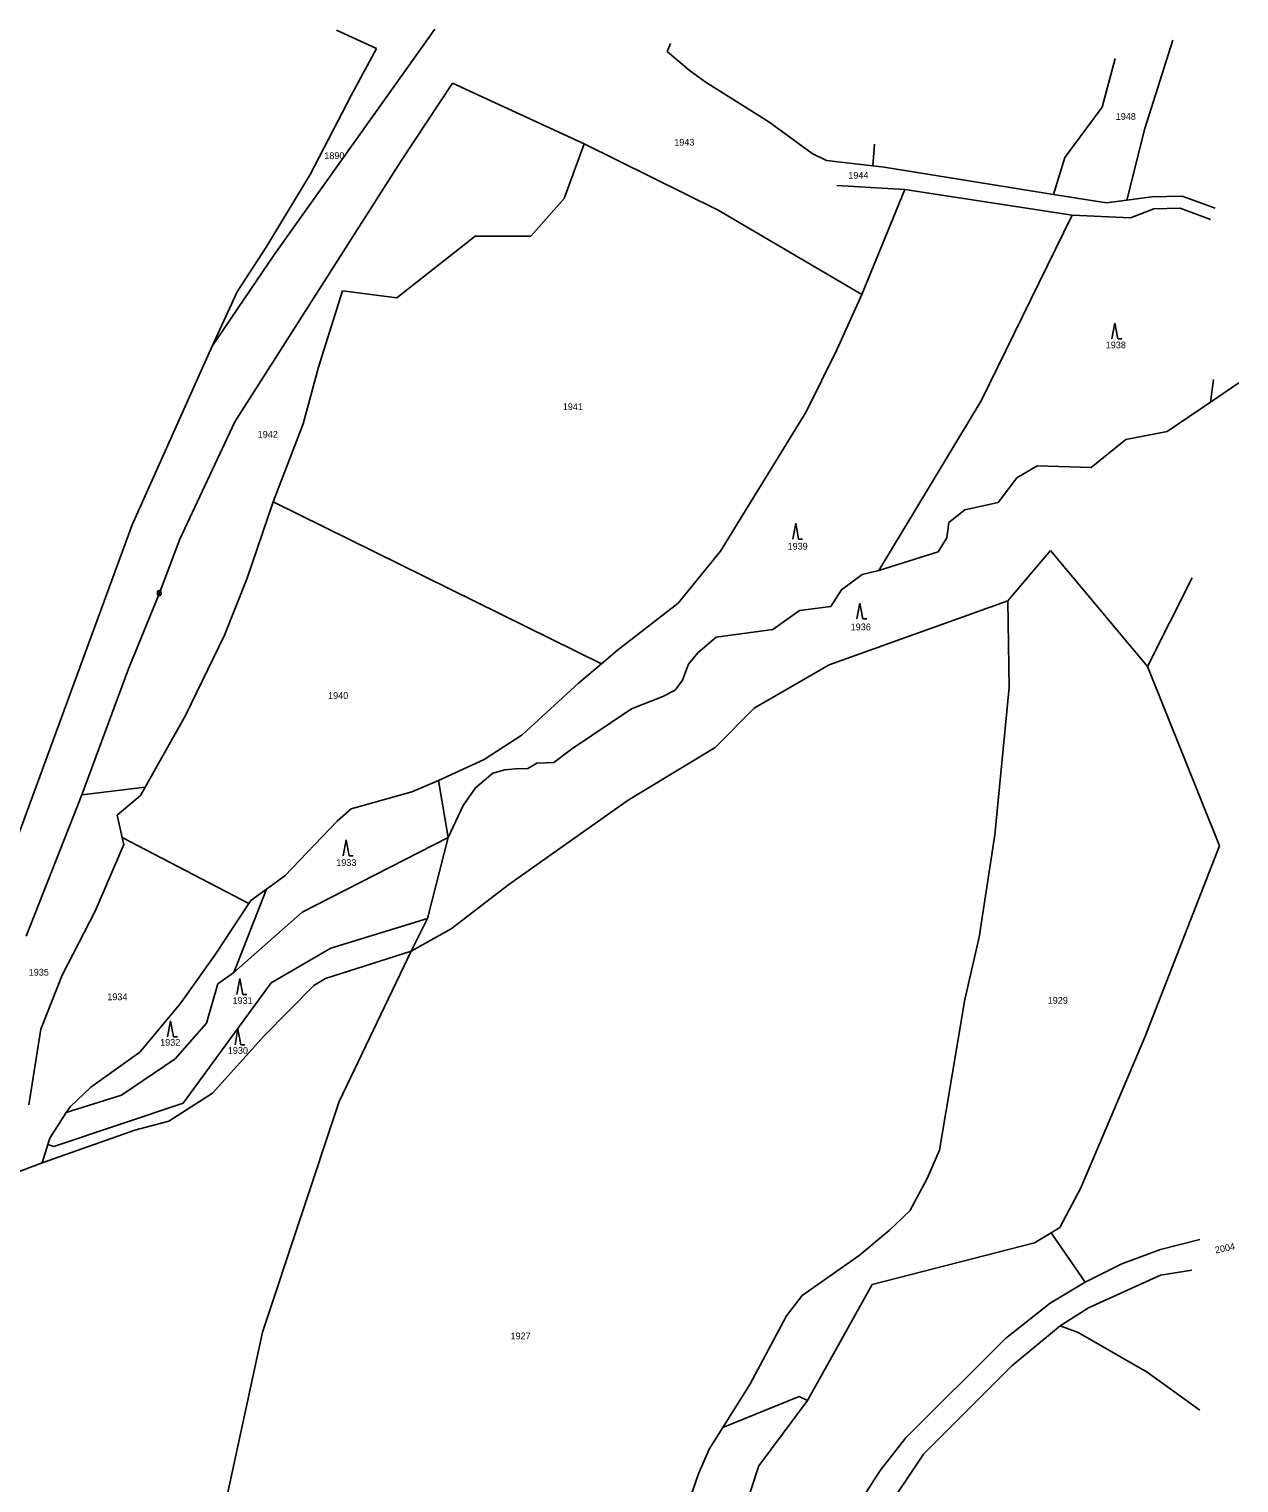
# Model space of a CAD drawing. Extents: x -801826 to -800592, y -1032871 to -1031813.
# Drawn here: x -800896.7 to -800592.7, y -1032178.1 to -1031812.7 of the extents above; entities that cross this region are included whole.
import ezdxf

# ---------------------------------------------------------------- set-up
doc = ezdxf.new("R2010")
doc.units = 0
for name, color, linetype in [('Vrstva 1', 7, 'Continuous'), ('Vrstva 18', 7, 'Continuous'), ('Vrstva 24', 7, 'Continuous'), ('Vrstva 25', 7, 'Continuous')]:
    doc.layers.add(name, color=color, linetype=linetype)

msp = doc.modelspace()

# ---------------------------------------------------------------- linework, layer by layer
at = {"layer": 'Vrstva 1'}
for p, q in [((-800794.72, -1031812.74), (-800834.92, -1031869.25)), ((-800819.49, -1031813), (-800809.4, -1031817.63)), ((-800735.53, -1031816.37), (-800736.38, -1031818.41)), ((-800616.36, -1031837.7), (-800609.3, -1031815.54)), ((-800815.75, -1031829.46), (-800809.4, -1031817.63)), ((-800730.87, -1031823.09), (-800736.38, -1031818.41)), ((-800623.79, -1031820.13), (-800627.09, -1031832.37)), ((-800726.8, -1031825.99), (-800730.87, -1031823.09)), ((-800803.37, -1031846.11), (-800790.33, -1031826.37)), ((-800757.2, -1031841.57), (-800790.33, -1031826.37)), ((-800710.79, -1031836.04), (-800726.8, -1031825.99)), ((-800826.05, -1031849.33), (-800815.75, -1031829.46)), ((-800627.09, -1031832.37), (-800636.49, -1031845.01)), ((-800699.93, -1031844), (-800710.79, -1031836.04)), ((-800620.85, -1031855.72), (-800616.36, -1031837.7)), ((-800762.25, -1031855.35), (-800757.2, -1031841.57)), ((-800757.2, -1031841.57), (-800723.58, -1031858.23)), ((-800684.7, -1031847.13), (-800684.25, -1031841.7)), ((-800696.34, -1031845.76), (-800699.93, -1031844)), ((-800684.7, -1031847.13), (-800696.34, -1031845.76)), ((-800636.49, -1031845.01), (-800639.27, -1031854.29)), ((-800845, -1031911.47), (-800803.37, -1031846.11)), ((-800837.11, -1031867.58), (-800826.05, -1031849.33)), ((-800681.88, -1031847.46), (-800684.7, -1031847.13)), ((-800639.27, -1031854.29), (-800681.88, -1031847.46)), ((-800693.74, -1031852.05), (-800676.64, -1031853.05)), ((-800676.64, -1031853.05), (-800687.5, -1031879.48)), ((-800676.64, -1031853.05), (-800634.57, -1031859.51)), ((-800770.59, -1031864.81), (-800762.25, -1031855.35)), ((-800626, -1031856.42), (-800639.27, -1031854.29)), ((-800620.85, -1031855.72), (-800626, -1031856.42)), ((-800614.71, -1031854.89), (-800620.85, -1031855.72)), ((-800607, -1031854.74), (-800614.71, -1031854.89)), ((-800598.7, -1031857.79), (-800607, -1031854.74)), ((-800723.58, -1031858.23), (-800687.5, -1031879.48)), ((-800657.45, -1031906.19), (-800634.57, -1031859.51)), ((-800634.57, -1031859.51), (-800619.94, -1031860.2)), ((-800619.94, -1031860.2), (-800614.11, -1031857.88)), ((-800614.11, -1031857.88), (-800607.51, -1031857.75)), ((-800607.51, -1031857.75), (-800599.87, -1031860.56)), ((-800844.38, -1031878.74), (-800837.11, -1031867.58)), ((-800804.3, -1031880.28), (-800784.63, -1031864.8)), ((-800784.63, -1031864.8), (-800770.59, -1031864.81)), ((-800834.92, -1031869.25), (-800850.7, -1031892.46)), ((-800823.97, -1031897.68), (-800817.92, -1031878.55)), ((-800817.92, -1031878.55), (-800804.3, -1031880.28)), ((-800850.7, -1031892.46), (-800844.38, -1031878.74)), ((-800687.5, -1031879.48), (-800693.77, -1031893.38)), ((-800850.7, -1031892.46), (-800870.77, -1031937.34)), ((-800693.77, -1031893.38), (-800701.44, -1031908.93)), ((-800827.84, -1031911.94), (-800823.97, -1031897.68)), ((-800599.88, -1031906.49), (-800599.09, -1031900.8)), ((-800592.71, -1031901.64), (-800599.88, -1031906.49)), ((-800683.21, -1031948.84), (-800657.45, -1031906.19)), ((-800599.88, -1031906.49), (-800610.76, -1031913.85)), ((-800858.84, -1031940.91), (-800845, -1031911.47)), ((-800701.44, -1031908.93), (-800722.96, -1031943.96)), ((-800835.33, -1031931.59), (-800827.84, -1031911.94)), ((-800610.76, -1031913.85), (-800621.1, -1031915.87)), ((-800621.1, -1031915.87), (-800629.85, -1031922.9)), ((-800648.49, -1031925.5), (-800653.17, -1031931.76)), ((-800643.39, -1031922.52), (-800648.49, -1031925.5)), ((-800629.85, -1031922.9), (-800643.39, -1031922.52)), ((-800841.93, -1031950.76), (-800835.33, -1031931.59)), ((-800752.91, -1031972.24), (-800835.33, -1031931.59)), ((-800653.17, -1031931.76), (-800661.55, -1031933.54)), ((-800665.57, -1031936.73), (-800666.12, -1031940.64)), ((-800661.55, -1031933.54), (-800665.57, -1031936.73)), ((-800870.77, -1031937.34), (-800899.17, -1032014.78)), ((-800666.12, -1031940.64), (-800668.31, -1031944.1)), ((-800864.01, -1031954.66), (-800858.84, -1031940.91)), ((-800722.96, -1031943.96), (-800733.57, -1031957.01)), ((-800668.31, -1031944.1), (-800683.21, -1031948.84)), ((-800650.8, -1031956.43), (-800640.07, -1031943.81)), ((-800640.07, -1031943.81), (-800615.65, -1031972.93)), ((-800847.59, -1031965.06), (-800841.93, -1031950.76)), ((-800692.56, -1031953.64), (-800687.41, -1031949.82)), ((-800687.41, -1031949.82), (-800683.21, -1031948.84)), ((-800604.42, -1031950.62), (-800615.65, -1031972.93)), ((-800871.72, -1031973.5), (-800864.01, -1031954.66)), ((-800695.28, -1031957.86), (-800692.56, -1031953.64)), ((-800733.57, -1031957.01), (-800748.84, -1031968.8)), ((-800709.84, -1031963.61), (-800703.11, -1031958.86)), ((-800703.11, -1031958.86), (-800695.28, -1031957.86)), ((-800695.63, -1031972.54), (-800650.8, -1031956.43)), ((-800650.8, -1031956.43), (-800650.43, -1031978.22)), ((-800857.42, -1031985.29), (-800847.59, -1031965.06)), ((-800728.67, -1031969.54), (-800724.04, -1031965.6)), ((-800724.04, -1031965.6), (-800709.84, -1031963.61)), ((-800748.84, -1031968.8), (-800752.91, -1031972.24)), ((-800731.01, -1031972.32), (-800728.67, -1031969.54)), ((-800883.47, -1032005.21), (-800871.72, -1031973.5)), ((-800752.91, -1031972.24), (-800758.68, -1031977.12)), ((-800732.56, -1031976.42), (-800731.01, -1031972.32)), ((-800714.48, -1031983.45), (-800695.63, -1031972.54)), ((-800615.65, -1031972.93), (-800597.63, -1032018.04)), ((-800758.68, -1031977.12), (-800772.81, -1031990.11)), ((-800734.36, -1031978.93), (-800732.56, -1031976.42)), ((-800745.32, -1031983.56), (-800737.45, -1031980.52)), ((-800737.45, -1031980.52), (-800734.36, -1031978.93)), ((-800650.43, -1031978.22), (-800654.02, -1032015.22)), ((-800760.39, -1031993.73), (-800745.32, -1031983.56)), ((-800724.34, -1031993.26), (-800714.48, -1031983.45)), ((-800857.42, -1031985.29), (-800867.57, -1032003.29)), ((-800772.81, -1031990.11), (-800782.38, -1031996.28)), ((-800764.86, -1031997.1), (-800760.39, -1031993.73)), ((-800746.18, -1032006.53), (-800724.34, -1031993.26)), ((-800782.38, -1031996.28), (-800793.84, -1032001.63)), ((-800780.16, -1031999.77), (-800777.18, -1031998.88)), ((-800777.18, -1031998.88), (-800774.44, -1031998.66)), ((-800774.44, -1031998.66), (-800771.4, -1031998.6)), ((-800771.4, -1031998.6), (-800769.08, -1031997.24)), ((-800769.08, -1031997.24), (-800764.86, -1031997.1)), ((-800793.84, -1032001.63), (-800800.56, -1032004.44)), ((-800793.84, -1032001.63), (-800791.36, -1032015.91)), ((-800784.57, -1032003.43), (-800780.16, -1031999.77)), ((-800897.43, -1032040.71), (-800883.47, -1032005.21)), ((-800883.47, -1032005.21), (-800867.57, -1032003.29)), ((-800874.53, -1032010.29), (-800868.73, -1032005.34)), ((-800867.57, -1032003.29), (-800868.73, -1032005.34)), ((-800800.56, -1032004.44), (-800815.76, -1032008.75)), ((-800787.61, -1032007.9), (-800784.57, -1032003.43)), ((-800776.15, -1032027.74), (-800746.18, -1032006.53)), ((-800815.76, -1032008.75), (-800819.31, -1032011.8)), ((-800791.36, -1032015.91), (-800787.61, -1032007.9)), ((-800873.28, -1032015.9), (-800874.53, -1032010.29)), ((-800819.31, -1032011.8), (-800832.46, -1032025.57)), ((-800872.89, -1032017.68), (-800873.28, -1032015.9)), ((-800841.45, -1032032.47), (-800873.28, -1032015.9)), ((-800828.11, -1032034.72), (-800791.36, -1032015.91)), ((-800796.62, -1032036.3), (-800791.36, -1032015.91)), ((-800654.02, -1032015.22), (-800657.95, -1032040.96)), ((-800880.13, -1032034.43), (-800872.89, -1032017.68)), ((-800597.63, -1032018.04), (-800616.35, -1032066.13)), ((-800832.46, -1032025.57), (-800837.08, -1032028.93)), ((-800790.61, -1032038.89), (-800776.15, -1032027.74)), ((-800845.22, -1032049.84), (-800837.08, -1032028.93)), ((-800840.99, -1032031.77), (-800841.45, -1032032.47)), ((-800837.08, -1032028.93), (-800840.99, -1032031.77)), ((-800888.39, -1032050.53), (-800880.13, -1032034.43)), ((-800841.45, -1032032.47), (-800850.03, -1032045.49)), ((-800845.22, -1032049.84), (-800828.11, -1032034.72)), ((-800820.9, -1032043.71), (-800796.62, -1032036.3)), ((-800800.72, -1032044.51), (-800796.62, -1032036.3)), ((-800800.72, -1032044.51), (-800790.61, -1032038.89)), ((-800657.95, -1032040.96), (-800661.54, -1032056.66)), ((-800850.03, -1032045.49), (-800858.78, -1032057.73)), ((-800835.89, -1032052.43), (-800820.9, -1032043.71)), ((-800822.24, -1032051.34), (-800800.72, -1032044.51)), ((-800800.72, -1032044.51), (-800818.82, -1032082.28)), ((-800849.24, -1032052.66), (-800845.22, -1032049.84)), ((-800893.77, -1032064.12), (-800888.39, -1032050.53)), ((-800858, -1032082.67), (-800835.89, -1032052.43)), ((-800852.15, -1032062.62), (-800849.24, -1032052.66)), ((-800837.6, -1032065.74), (-800825.18, -1032053.11)), ((-800825.18, -1032053.11), (-800822.24, -1032051.34)), ((-800661.54, -1032056.66), (-800667.98, -1032094.53)), ((-800858.78, -1032057.73), (-800868.91, -1032069.9)), ((-800896.78, -1032083.1), (-800893.77, -1032064.12)), ((-800860.01, -1032071.52), (-800852.15, -1032062.62)), ((-800850.6, -1032080.16), (-800837.6, -1032065.74)), ((-800616.35, -1032066.13), (-800632.46, -1032103.98)), ((-800868.91, -1032069.9), (-800881.18, -1032078.69)), ((-800873.48, -1032080.68), (-800860.01, -1032071.52)), ((-800881.18, -1032078.69), (-800886.4, -1032083.58)), ((-800890.48, -1032093.55), (-800858, -1032082.67)), ((-800887.35, -1032085.06), (-800873.48, -1032080.68)), ((-800861.62, -1032087.2), (-800850.6, -1032080.16)), ((-800818.82, -1032082.28), (-800838.07, -1032140.21)), ((-800887.35, -1032085.06), (-800891.47, -1032091.5)), ((-800886.4, -1032083.58), (-800887.35, -1032085.06)), ((-800893.41, -1032097.71), (-800870.11, -1032089.46)), ((-800870.11, -1032089.46), (-800861.62, -1032087.2)), ((-800891.95, -1032093.05), (-800893.41, -1032097.71)), ((-800891.47, -1032091.5), (-800891.95, -1032093.05)), ((-800891.95, -1032093.05), (-800890.48, -1032093.55)), ((-800893.41, -1032097.71), (-800903.84, -1032101.64)), ((-800667.98, -1032094.53), (-800671.03, -1032101.61)), ((-800671.03, -1032101.61), (-800675.38, -1032109.78)), ((-800632.46, -1032103.98), (-800637.73, -1032113.97)), ((-800675.38, -1032109.78), (-800680.51, -1032114.63)), ((-800680.51, -1032114.63), (-800688.09, -1032120.97)), ((-800639.92, -1032115.3), (-800644.04, -1032117.81)), ((-800637.73, -1032113.97), (-800639.92, -1032115.3)), ((-800639.92, -1032115.3), (-800631.36, -1032127.65)), ((-800644.04, -1032117.81), (-800684.85, -1032128.26)), ((-800612.43, -1032119.51), (-800622.1, -1032123.07)), ((-800602.5, -1032116.95), (-800612.43, -1032119.51)), ((-800688.09, -1032120.97), (-800702.44, -1032131.04)), ((-800622.1, -1032123.07), (-800631.36, -1032127.65)), ((-800630.5, -1032134.09), (-800612.42, -1032125.89)), ((-800612.42, -1032125.89), (-800604.51, -1032124.63)), ((-800684.85, -1032128.26), (-800701.1, -1032157.42)), ((-800631.36, -1032127.65), (-800640.11, -1032132.98)), ((-800702.44, -1032131.04), (-800706.38, -1032136.18)), ((-800640.11, -1032132.98), (-800651.33, -1032141.83)), ((-800637.65, -1032138.64), (-800630.5, -1032134.09)), ((-800706.38, -1032136.18), (-800715.64, -1032153.39)), ((-800838.07, -1032140.21), (-800861.49, -1032248.55)), ((-800649.8, -1032148.73), (-800637.65, -1032138.64)), ((-800633.09, -1032140.37), (-800637.65, -1032138.64)), ((-800615.78, -1032150.26), (-800633.09, -1032140.37)), ((-800651.33, -1032141.83), (-800676.45, -1032166.92)), ((-800671.93, -1032170.88), (-800649.8, -1032148.73)), ((-800602.54, -1032159.88), (-800615.78, -1032150.26)), ((-800715.64, -1032153.39), (-800722.41, -1032164.17)), ((-800722.41, -1032164.17), (-800703.23, -1032156.45)), ((-800701.1, -1032157.42), (-800713.36, -1032173.84)), ((-800703.23, -1032156.45), (-800701.1, -1032157.42)), ((-800722.41, -1032164.17), (-800725.84, -1032169.64)), ((-800676.45, -1032166.92), (-800682.84, -1032174.99)), ((-800725.84, -1032169.64), (-800728.49, -1032175.86)), ((-800682.78, -1032186.99), (-800671.93, -1032170.88)), ((-800713.36, -1032173.84), (-800718.08, -1032188.22)), ((-800728.49, -1032175.86), (-800731.3, -1032183.84)), ((-800682.84, -1032174.99), (-800688.39, -1032183.65))]:
    msp.add_line(p, q, dxfattribs=at)
at = {"layer": 'Vrstva 24'}
for radius in [0.5, 0.0364]:
    msp.add_circle((-800864.01, -1031954.66), radius, dxfattribs=at)
msp.add_arc((-800864.01, -1031954.29), 0.45, 344.4473, 196.3778, dxfattribs=at)
at = {"layer": 'Vrstva 25'}
for p, q in [((-800623.88, -1031886.63), (-800624.61, -1031890.63)), ((-800623.88, -1031886.63), (-800623.15, -1031890.63)), ((-800623.15, -1031890.63), (-800622.15, -1031890.63)), ((-800704.07, -1031936.95), (-800704.81, -1031940.95)), ((-800704.07, -1031936.95), (-800703.34, -1031940.95)), ((-800703.34, -1031940.95), (-800702.34, -1031940.95)), ((-800687.95, -1031956.99), (-800688.69, -1031960.99)), ((-800687.95, -1031956.99), (-800687.22, -1031960.99)), ((-800687.22, -1031960.99), (-800686.22, -1031960.99)), ((-800817.02, -1032016.49), (-800817.76, -1032020.49)), ((-800817.02, -1032016.49), (-800816.29, -1032020.49)), ((-800816.29, -1032020.49), (-800815.29, -1032020.49)), ((-800843.75, -1032051.36), (-800844.48, -1032055.36)), ((-800843.75, -1032051.36), (-800843.02, -1032055.36)), ((-800843.02, -1032055.36), (-800842.02, -1032055.36)), ((-800861.18, -1032061.98), (-800861.92, -1032065.98)), ((-800861.18, -1032061.98), (-800860.45, -1032065.98)), ((-800844.22, -1032064.03), (-800844.96, -1032068.03)), ((-800844.22, -1032064.03), (-800843.49, -1032068.03)), ((-800860.45, -1032065.98), (-800859.45, -1032065.98)), ((-800843.49, -1032068.03), (-800842.49, -1032068.03))]:
    msp.add_line(p, q, dxfattribs=at)

# ---------------------------------------------------------------- texts
at = {"layer": 'Vrstva 18'}
for s, p in [('1948', (-800623.66, -1031835.55)), ('1943', (-800734.59, -1031842.03)), ('1890', (-800822.53, -1031845.4)), ('1944', (-800690.86, -1031850.34)), ('1938', (-800626.17, -1031892.99)), ('1941', (-800762.59, -1031908.49)), ('1942', (-800839.26, -1031915.45)), ('1939', (-800706.12, -1031943.57)), ('1936', (-800690.26, -1031963.84)), ('1940', (-800821.57, -1031981.09)), ('1933', (-800819.52, -1032023.07)), ('1935', (-800896.79, -1032050.63)), ('1934', (-800877.05, -1032056.81)), ('1931', (-800845.59, -1032057.76)), ('1929', (-800640.75, -1032057.69)), ('1932', (-800863.76, -1032068.24)), ('1930', (-800846.76, -1032070.29)), ('1927', (-800775.73, -1032142.04))]:
    msp.add_text(s, height=1.7, dxfattribs=at).set_placement(p)
msp.add_text('2004', height=1.7, rotation=11.5737, dxfattribs=at).set_placement((-800598.53, -1032120.47))

doc.saveas('drawing.dxf')
